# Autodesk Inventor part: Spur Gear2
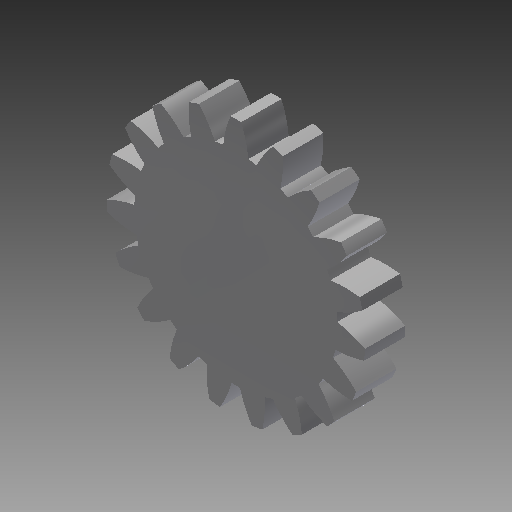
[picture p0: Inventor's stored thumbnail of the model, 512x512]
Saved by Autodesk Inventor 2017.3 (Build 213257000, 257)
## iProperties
Created: 2020-03
Part Number: Spur Gear2
Material: Steel
Document SubType Name: Modeling
Designer: Tim_G
Categories: <?xml version="1.0" encoding="UTF-16"?> <MemberInstance><Categories><FamilyTemplate><FamilyTemplateParameter ValueType="xs:double" Id="1" ObjectReferenceKey="da
Density: 1 g/cm^3
Appearance: Steel
CustomPartVersion: 1
Author: Tim_G
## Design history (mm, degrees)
sketch "Sketch1"
  geometry: C1 r 15.991 at (0, 0)
  constraints: 1 centre point
  dimensions: "d0" = 31.98165 diameter of C1 (= da_da)
extrude "Extrusion1" new body sketch "Sketch1" distance "d1" = 5 (= da_b); taper "d2" = 0 deg
workplane "Work Plane2"
sketch "Sketch2"
  geometry: C1 r 15.991 at (0, 0) reference; C2 r 14.468 at (0, 0)
  constraints: 1 centre point, 1 coincident
  dimensions: "d3" = 28.93578 diameter of C2 (= da_dw)
feature "Pitch Diameter" sketch "Sketch2" dims "d4" = 10, "d5" = 0
workplane "Work Plane8"
workplane "Work Plane9"
feature "Spur Gear" dims "da_b" = 5, "da_d" = 28.93578, "da_aw" = 22.84404, "da_da" = 31.98165, "da_df" = 25.12844, "da_dw" = 28.93578, angle "da_beta" = 0 deg, "da_lefttooth" = 0, "da_righttooth" = 0
body "Solid1"
body "Srf1"
other parameters: "d16" = 22.84404 (= da_aw), "d17" = 0, "d34" = 1.65347 (computed from da_z), "d39" = 0, "d41" = 0, "d43" = 22.84404 (= da_aw), "d46" = 22.84404 (= da_aw), "d47" = 0, "d48" = 0
